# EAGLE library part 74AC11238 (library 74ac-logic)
3 to 8 line DECODER/DEMULTIPLEXER
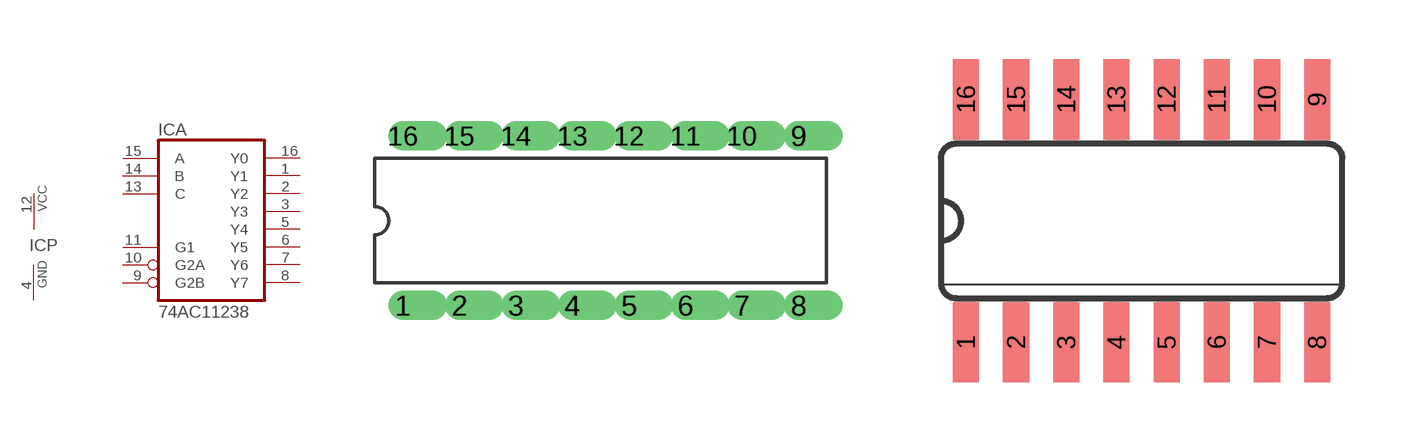
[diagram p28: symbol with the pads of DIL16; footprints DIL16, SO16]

Designator prefix IC; gates A=7411238 P=PWRN

## 74AC11238  [DIL16]
1  A:Y1  out
2  A:Y2  out
3  A:Y3  out
4  P:GND  pwr
5  A:Y4  out
6  A:Y5  out
7  A:Y6  out
8  A:Y7  out
9  A:G2B  in
10  A:G2A  in
11  A:G1  in
12  P:VCC  pwr
13  A:C  in
14  A:B  in
15  A:A  in
16  A:Y0  out

## 74AC11238D  [SO16]
Pads as for DIL16

## Footprint DIL16 (pad centres in mm)
Dual In Line
drill 0.813 offset: 1 -8.89,-3.81; 2 -6.35,-3.81; 3 -3.81,-3.81; 4 -1.27,-3.81; 5 1.27,-3.81; 6 3.81,-3.81; 7 6.35,-3.81; 8 8.89,-3.81; 9 8.89,3.81; 10 6.35,3.81; 11 3.81,3.81; 12 1.27,3.81; 13 -1.27,3.81; 14 -3.81,3.81; 15 -6.35,3.81; 16 -8.89,3.81

## Footprint SO16 (pad centres in mm)
Small Outline package 150 mil
smd 0.66 x 2.032: 1 -4.445,-3.073; 2 -3.175,-3.073; 3 -1.905,-3.073; 4 -0.635,-3.073; 5 0.635,-3.073; 6 1.905,-3.073; 7 3.175,-3.073; 8 4.445,-3.073; 9 4.445,3.073; 10 3.175,3.073; 11 1.905,3.073; 12 0.635,3.073; 13 -0.635,3.073; 14 -1.905,3.073; 15 -3.175,3.073; 16 -4.445,3.073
